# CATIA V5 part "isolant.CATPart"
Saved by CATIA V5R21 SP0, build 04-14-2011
Part number: isolant
Bounding box of the stored display mesh (mm): x -39 to 39, y -26.5 to 26.5, z 0 to 1
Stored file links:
  C:\Users\zerma\Pictures\CAO\isolant.CATPart
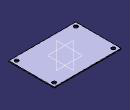
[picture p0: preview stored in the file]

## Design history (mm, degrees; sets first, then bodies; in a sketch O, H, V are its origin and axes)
Body1 (main body)
  Sketch1 on xy-plane, origin (0, 0, 0), H (1, 0, 0), V (0, 1, 0)
    line L1 (39, 26.5) -> (39, -26.5)
    line L2 (39, -26.5) -> (-39, -26.5)
    line L3 (-39, -26.5) -> (-39, 26.5)
    line L4 (-39, 26.5) -> (39, 26.5)
    circle A1 centre (34.4, -21.9) radius 2.1
    point P5 (34.4, -21.9)
    circle A2 centre (-34.4, -21.9) radius 2.1
    circle A3 centre (-34.4, 21.9) radius 2.1
    circle A4 centre (34.4, 21.9) radius 2.1
    length L4 = 78
    length L1 = 53
    radius A1 = 2.1
    distance P5 L2 = 4.6
    distance L1 P5 = 4.6
    vertical: L1 V, L3 V
    horizontal: L2 H, L4 H
    equidistance: L1 L3 O, L2 L4 O
    symmetry: A1 A2 V, A2 A3 H, A3 A4 V
  Pad1: profile Sketch1, direction (0, 0, 1), length 1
